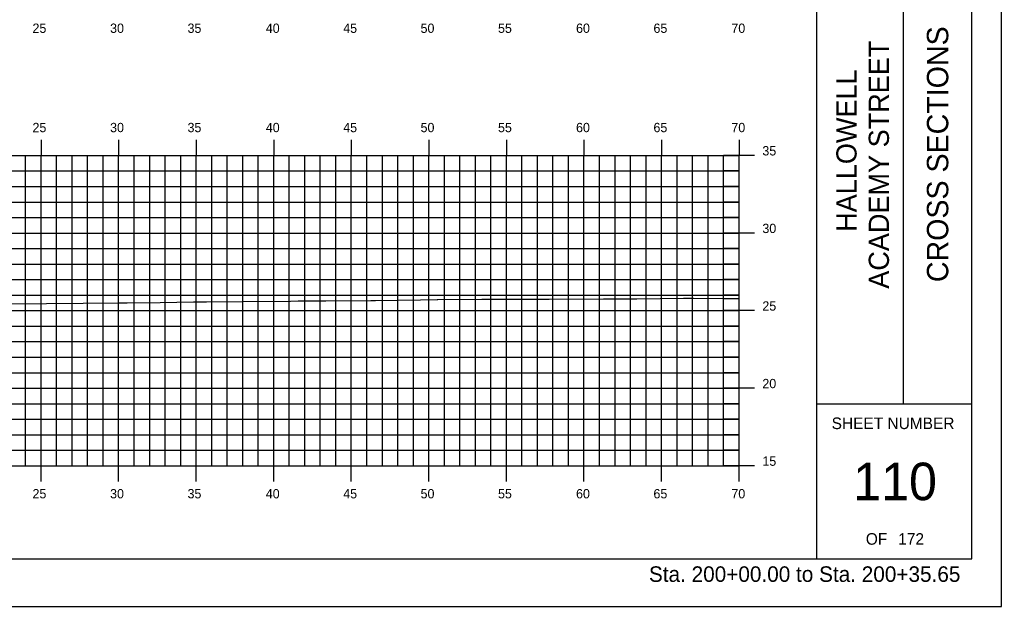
# Model space of a CAD drawing. Extents: x 1023237 to 1023407, y 394697 to 394807.
# Drawn here: x 1023343.3 to 1023406.6, y 394696.5 to 394734.4 of the extents above; entities that cross this region are included whole.
import ezdxf

# ---------------------------------------------------------------- set-up
doc = ezdxf.new("R2010")
doc.units = 0
for name, color, linetype in [('BORDER', 7, 'Continuous'), ('H_V ANNOTATION', 7, 'Continuous'), ('HIGHWAY_TITLE', 7, 'Continuous'), ('MAJOR', 7, 'Continuous'), ('MINOR', 7, 'Continuous'), ('PLOT BOUNDARY', 7, 'Continuous'), ('S_Roadway_Centerline', 7, 'Continuous')]:
    doc.layers.add(name, color=color, linetype=linetype)

msp = doc.modelspace()

# ---------------------------------------------------------------- linework, layer by layer
at = {"layer": 'BORDER'}
for p, q in [((1023394.664, 394699.607), (1023394.664, 394804.61)), ((1023404.664, 394699.607), (1023404.664, 394804.607)), ((1023400.255, 394709.61), (1023400.255, 394744.61)), ((1023394.664, 394709.61), (1023404.664, 394709.61)), ((1023244.664, 394699.607), (1023404.664, 394699.607))]:
    msp.add_line(p, q, dxfattribs=at)
at = {"layer": 'MAJOR'}
for p, q in [((1023344.663, 394726.609), (1023344.663, 394725.607)), ((1023349.663, 394726.609), (1023349.663, 394725.607)), ((1023354.663, 394726.609), (1023354.663, 394725.607)), ((1023359.663, 394726.609), (1023359.663, 394725.607)), ((1023364.663, 394726.609), (1023364.663, 394725.607)), ((1023369.663, 394726.609), (1023369.663, 394725.607)), ((1023374.663, 394726.609), (1023374.663, 394725.607)), ((1023379.663, 394726.609), (1023379.663, 394725.607)), ((1023384.663, 394726.609), (1023384.663, 394725.607)), ((1023389.663, 394726.609), (1023389.663, 394725.607)), ((1023249.663, 394725.607), (1023389.663, 394725.607)), ((1023344.663, 394705.607), (1023344.663, 394725.607)), ((1023349.663, 394705.607), (1023349.663, 394725.607)), ((1023354.663, 394705.607), (1023354.663, 394725.607)), ((1023359.663, 394705.607), (1023359.663, 394725.607)), ((1023364.663, 394705.607), (1023364.663, 394725.607)), ((1023369.663, 394705.607), (1023369.663, 394725.607)), ((1023374.663, 394705.607), (1023374.663, 394725.607)), ((1023379.663, 394705.607), (1023379.663, 394725.607)), ((1023384.663, 394705.607), (1023384.663, 394725.607)), ((1023390.665, 394725.607), (1023388.661, 394725.607)), ((1023389.663, 394705.607), (1023389.663, 394725.607)), ((1023249.663, 394720.607), (1023389.663, 394720.607)), ((1023390.665, 394720.607), (1023388.661, 394720.607)), ((1023249.663, 394715.607), (1023389.663, 394715.607)), ((1023390.665, 394715.607), (1023388.661, 394715.607)), ((1023249.663, 394710.607), (1023389.663, 394710.607)), ((1023390.665, 394710.607), (1023388.661, 394710.607)), ((1023249.663, 394705.607), (1023389.663, 394705.607)), ((1023344.663, 394704.605), (1023344.663, 394705.607)), ((1023349.663, 394704.605), (1023349.663, 394705.607)), ((1023354.663, 394704.605), (1023354.663, 394705.607)), ((1023359.663, 394704.605), (1023359.663, 394705.607)), ((1023364.663, 394704.605), (1023364.663, 394705.607)), ((1023369.663, 394704.605), (1023369.663, 394705.607)), ((1023374.663, 394704.605), (1023374.663, 394705.607)), ((1023379.663, 394704.605), (1023379.663, 394705.607)), ((1023384.663, 394704.605), (1023384.663, 394705.607)), ((1023390.665, 394705.607), (1023388.661, 394705.607)), ((1023389.663, 394704.605), (1023389.663, 394705.607))]:
    msp.add_line(p, q, dxfattribs=at)
at = {"layer": 'MINOR'}
for p, q in [((1023343.663, 394705.607), (1023343.663, 394725.607)), ((1023345.663, 394705.607), (1023345.663, 394725.607)), ((1023346.663, 394705.607), (1023346.663, 394725.607)), ((1023347.663, 394705.607), (1023347.663, 394725.607)), ((1023348.663, 394705.607), (1023348.663, 394725.607)), ((1023350.663, 394705.607), (1023350.663, 394725.607)), ((1023351.663, 394705.607), (1023351.663, 394725.607)), ((1023352.663, 394705.607), (1023352.663, 394725.607)), ((1023353.663, 394705.607), (1023353.663, 394725.607)), ((1023355.663, 394705.607), (1023355.663, 394725.607)), ((1023356.663, 394705.607), (1023356.663, 394725.607)), ((1023357.663, 394705.607), (1023357.663, 394725.607)), ((1023358.663, 394705.607), (1023358.663, 394725.607)), ((1023360.663, 394705.607), (1023360.663, 394725.607)), ((1023361.663, 394705.607), (1023361.663, 394725.607)), ((1023362.663, 394705.607), (1023362.663, 394725.607)), ((1023363.663, 394705.607), (1023363.663, 394725.607)), ((1023365.663, 394705.607), (1023365.663, 394725.607)), ((1023366.663, 394705.607), (1023366.663, 394725.607)), ((1023367.663, 394705.607), (1023367.663, 394725.607)), ((1023368.663, 394705.607), (1023368.663, 394725.607)), ((1023370.663, 394705.607), (1023370.663, 394725.607)), ((1023371.663, 394705.607), (1023371.663, 394725.607)), ((1023372.663, 394705.607), (1023372.663, 394725.607)), ((1023373.663, 394705.607), (1023373.663, 394725.607)), ((1023375.663, 394705.607), (1023375.663, 394725.607)), ((1023376.663, 394705.607), (1023376.663, 394725.607)), ((1023377.663, 394705.607), (1023377.663, 394725.607)), ((1023378.663, 394705.607), (1023378.663, 394725.607)), ((1023380.663, 394705.607), (1023380.663, 394725.607)), ((1023381.663, 394705.607), (1023381.663, 394725.607)), ((1023382.663, 394705.607), (1023382.663, 394725.607)), ((1023383.663, 394705.607), (1023383.663, 394725.607)), ((1023385.663, 394705.607), (1023385.663, 394725.607)), ((1023386.663, 394705.607), (1023386.663, 394725.607)), ((1023387.663, 394705.607), (1023387.663, 394725.607)), ((1023388.663, 394705.607), (1023388.663, 394725.607)), ((1023249.663, 394724.607), (1023389.663, 394724.607)), ((1023389.663, 394724.607), (1023388.661, 394724.607)), ((1023249.663, 394723.607), (1023389.663, 394723.607)), ((1023389.663, 394723.607), (1023388.661, 394723.607)), ((1023249.663, 394722.607), (1023389.663, 394722.607)), ((1023389.663, 394722.607), (1023388.661, 394722.607)), ((1023249.663, 394721.607), (1023389.663, 394721.607)), ((1023389.663, 394721.607), (1023388.661, 394721.607)), ((1023249.663, 394719.607), (1023389.663, 394719.607)), ((1023389.663, 394719.607), (1023388.661, 394719.607)), ((1023249.663, 394718.607), (1023389.663, 394718.607)), ((1023389.663, 394718.607), (1023388.661, 394718.607)), ((1023249.663, 394717.607), (1023389.663, 394717.607)), ((1023389.663, 394717.607), (1023388.661, 394717.607)), ((1023249.663, 394716.607), (1023389.663, 394716.607)), ((1023389.663, 394716.607), (1023388.661, 394716.607)), ((1023249.663, 394714.607), (1023389.663, 394714.607)), ((1023389.663, 394714.607), (1023388.661, 394714.607)), ((1023249.663, 394713.607), (1023389.663, 394713.607)), ((1023389.663, 394713.607), (1023388.661, 394713.607)), ((1023249.663, 394712.607), (1023389.663, 394712.607)), ((1023389.663, 394712.607), (1023388.661, 394712.607)), ((1023249.663, 394711.607), (1023389.663, 394711.607)), ((1023389.663, 394711.607), (1023388.661, 394711.607)), ((1023249.663, 394709.607), (1023389.663, 394709.607)), ((1023389.663, 394709.607), (1023388.661, 394709.607)), ((1023249.663, 394708.607), (1023389.663, 394708.607)), ((1023389.663, 394708.607), (1023388.661, 394708.607)), ((1023249.663, 394707.607), (1023389.663, 394707.607)), ((1023389.663, 394707.607), (1023388.661, 394707.607)), ((1023249.663, 394706.607), (1023389.663, 394706.607)), ((1023389.663, 394706.607), (1023388.661, 394706.607))]:
    msp.add_line(p, q, dxfattribs=at)
at = {"layer": 'PLOT BOUNDARY'}
msp.add_lwpolyline([(1023236.57, 394696.548), (1023406.57, 394696.548), (1023406.57, 394806.548), (1023236.57, 394806.548)], close=True, dxfattribs=at)
at = {"layer": 'S_Roadway_Centerline'}
msp.add_lwpolyline([(1023342.724, 394716.038), (1023345.005, 394716.062), (1023345.014, 394716.063), (1023345.021, 394716.063), (1023347.379, 394716.09), (1023349.685, 394716.112), (1023350.22, 394716.118), (1023352.343, 394716.138), (1023354.486, 394716.165), (1023354.757, 394716.168), (1023354.758, 394716.168), (1023354.79, 394716.168), (1023354.803, 394716.168), (1023355.322, 394716.172), (1023357.62, 394716.195), (1023360.747, 394716.223), (1023361.244, 394716.228), (1023361.337, 394716.229), (1023361.873, 394716.234), (1023363.011, 394716.241), (1023365.916, 394716.264), (1023366.228, 394716.266), (1023369.128, 394716.295), (1023370.197, 394716.328), (1023370.234, 394716.329), (1023373.084, 394716.345), (1023373.185, 394716.346), (1023376.645, 394716.342), (1023377.416, 394716.346), (1023380.915, 394716.358), (1023381.786, 394716.357), (1023383.075, 394716.366), (1023386.072, 394716.407), (1023386.718, 394716.405), (1023388.614, 394716.389), (1023389.663, 394716.396)], dxfattribs=at)

# ---------------------------------------------------------------- texts
at = {"layer": 'BORDER'}
for s, height, rotation, p in [('CROSS SECTIONS', 1.37787, 90, (1023403.148, 394717.444)), ('SHEET NUMBER', 0.74527, 360, (1023395.629, 394707.973)), ('110', 2.4194, 360, (1023397.019, 394703.389)), ('OF', 0.7453, 360, (1023397.831, 394700.52)), ('172', 0.7453, 360, (1023399.92, 394700.52))]:
    msp.add_text(s, height=height, rotation=rotation, dxfattribs=at).set_placement(p)
at = {"layer": 'H_V ANNOTATION'}
for s, height, p in [('25', 0.6, (1023344.109, 394733.507)), ('30', 0.6, (1023349.112, 394733.507)), ('35', 0.6, (1023354.104, 394733.507)), ('40', 0.6, (1023359.15, 394733.507)), ('45', 0.6, (1023364.142, 394733.507)), ('50', 0.6, (1023369.128, 394733.507)), ('55', 0.6, (1023374.12, 394733.507)), ('60', 0.6, (1023379.15, 394733.507)), ('65', 0.6, (1023384.142, 394733.507)), ('70', 0.6, (1023389.165, 394733.507)), ('25', 0.6, (1023344.109, 394727.107)), ('30', 0.6, (1023349.112, 394727.107)), ('35', 0.6, (1023354.104, 394727.107)), ('40', 0.6, (1023359.15, 394727.107)), ('45', 0.6, (1023364.142, 394727.107)), ('50', 0.6, (1023369.128, 394727.107)), ('55', 0.6, (1023374.12, 394727.107)), ('60', 0.6, (1023379.15, 394727.107)), ('65', 0.6, (1023384.142, 394727.107)), ('70', 0.6, (1023389.165, 394727.107)), ('35', 0.6, (1023391.163, 394725.607)), ('30', 0.6, (1023391.163, 394720.607)), ('25', 0.6, (1023391.163, 394715.607)), ('20', 0.6, (1023391.163, 394710.607)), ('15', 0.6, (1023391.163, 394705.607)), ('25', 0.6, (1023344.109, 394703.507)), ('30', 0.6, (1023349.112, 394703.507)), ('35', 0.6, (1023354.104, 394703.507)), ('40', 0.6, (1023359.15, 394703.507)), ('45', 0.6, (1023364.142, 394703.507)), ('50', 0.6, (1023369.128, 394703.507)), ('55', 0.6, (1023374.12, 394703.507)), ('60', 0.6, (1023379.15, 394703.507)), ('65', 0.6, (1023384.142, 394703.507)), ('70', 0.6, (1023389.165, 394703.507)), ('Sta. 200+00.00 to Sta. 200+35.65', 1.0002, (1023383.85, 394698.126))]:
    msp.add_text(s, height=height, dxfattribs=at).set_placement(p)
at = {"layer": 'HIGHWAY_TITLE'}
for s, height, p in [('ACADEMY STREET', 1.30428, (1023399.323, 394717.018)), ('HALLOWELL', 1.3043, (1023397.236, 394720.684))]:
    msp.add_text(s, height=height, rotation=90, dxfattribs=at).set_placement(p)

doc.saveas('drawing.dxf')
